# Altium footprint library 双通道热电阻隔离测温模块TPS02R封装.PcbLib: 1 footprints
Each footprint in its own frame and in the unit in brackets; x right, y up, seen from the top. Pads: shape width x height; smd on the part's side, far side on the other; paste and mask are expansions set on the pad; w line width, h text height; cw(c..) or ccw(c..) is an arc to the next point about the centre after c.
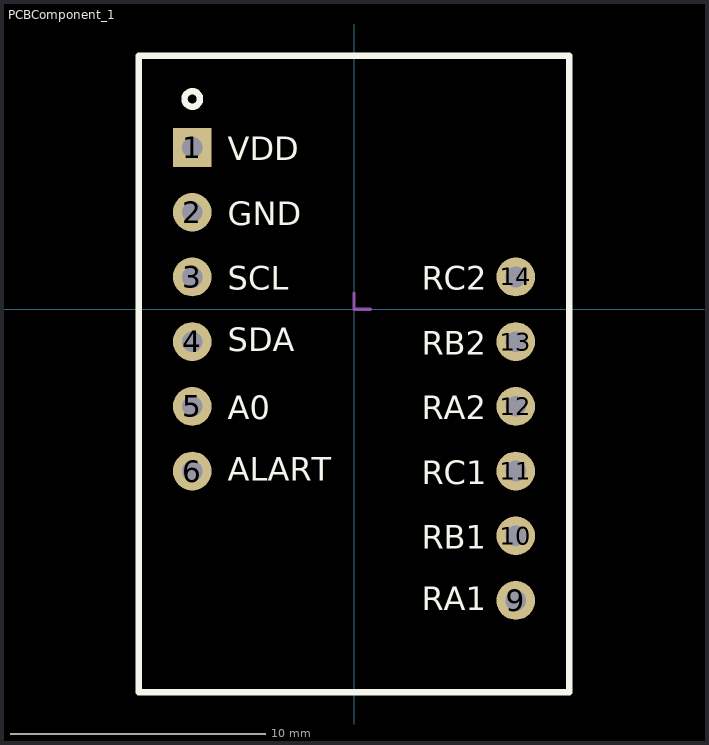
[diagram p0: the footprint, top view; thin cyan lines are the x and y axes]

## PCBComponent_1 [mil]
pads (12):
  rect 60x60 hole 32: 1(-250,250)
  round 60 hole 32: 2(-250,150) 3(-250,50) 4(-250,-50) 5(-250,-150) 6(-250,-250) 9(250,-450) 10(250,-350) 11(250,-250) 12(250,-150) 13(250,-50) 14(250,50)
Top Overlay:
  circle w10: c-250,325 r12
  lines w10: -332.68,-591.73 -332.68,391.73 332.68,391.73 332.68,-591.73 -332.68,-591.73
  text "A0" at -195,-170 h36
  text "ALART" at -195,-265 h36
  text "SDA" at -195,-65 h36
  text "SCL" at -195,30 h36
  text "GND" at -195,130 h36
  text "VDD" at -195,230 h36
  text "RB1" at 105,-370 h36
  text "RA1" at 105,-465 h36
  text "RC1" at 105,-270 h36
  text "RA2" at 105,-170 h36
  text "RB2" at 105,-70 h36
  text "RC2" at 105,30 h36
Mechanical 15:
  lines w5: 0,25 0,0 25,0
